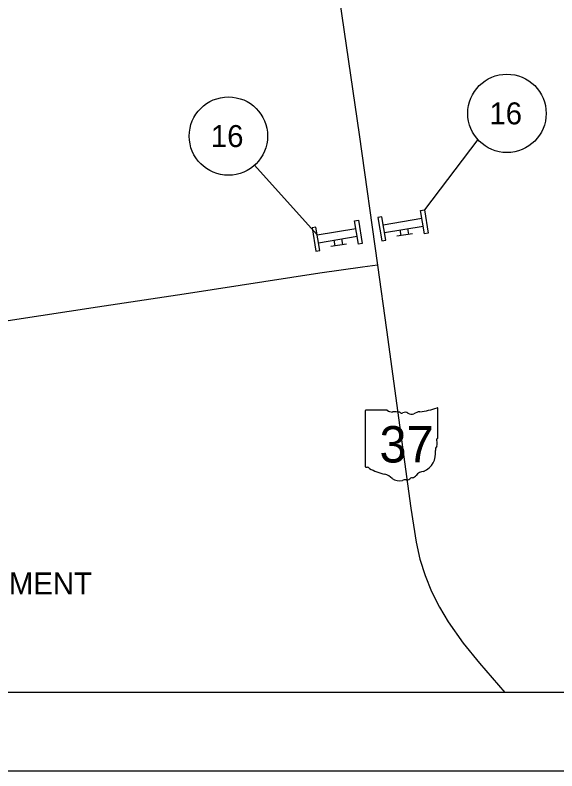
# Model space of a CAD drawing. Extents: x 0 to 860, y 0 to 513.
# Drawn here: x 543.6 to 612.7, y 0 to 96.5 of the extents above; entities that cross this region are included whole.
import ezdxf

# ---------------------------------------------------------------- set-up
doc = ezdxf.new("R2010")
doc.units = 0
for name, color, linetype in [('GM_X_State_Route', 7, 'Continuous'), ('GM_X_State_Shield', 7, 'Continuous'), ('MT_P_Cells', 7, 'Continuous'), ('MT_P_Text', 7, 'Continuous'), ('SH_Border', 7, 'Continuous'), ('SH_Cut_Line', 7, 'Continuous'), ('SH_Text', 7, 'Continuous')]:
    doc.layers.add(name, color=color, linetype=linetype)

msp = doc.modelspace()

# ---------------------------------------------------------------- linework, layer by layer
at = {"layer": 'GM_X_State_Route'}
for p, q in [((602.614, 80.579), (595.8, 71.598)), ((574.144, 77.301), (582.122, 68.405))]:
    msp.add_line(p, q, dxfattribs=at)
msp.add_lwpolyline([(562.698, 192.909), (570.661, 166.428), (575.44, 147.058), (579.85, 129.649), (582.628, 114.786), (585.257, 96.374), (587.475, 81.221), (589.804, 64.545), (590.968, 56.308), (594.05, 33.537), (594.743, 29.195), (595.231, 27.041), (595.885, 24.93), (596.718, 22.881), (597.709, 20.902), (598.844, 19.007), (600.762, 16.311), (602.842, 13.754), (606.072, 10)], dxfattribs=at)
for centre in [(606.332, 83.923), (570.805, 81.023)]:
    msp.add_circle(centre, 5, dxfattribs=at)
at = {"layer": 'GM_X_State_Shield'}
for p, q in [((588.246, 45.911), (588.246, 38.866)), ((591.055, 46.032), (588.337, 46.032)), ((597.527, 42.521), (597.527, 46.206)), ((597.526, 42.522), (597.527, 42.521))]:
    msp.add_line(p, q, dxfattribs=at)
for centre, radius, start, end in [((594.221, 55.635), 9.842, 275.84447, 288.90645), ((597.424, 46.222), 0.103, 351.86209, 97.738), ((588.352, 45.926), 0.108, 98.1301, 188.1301), ((591.703, 46.849), 1.043, 231.61951, 271.11188), ((592.048, 42.077), 3.744, 80.48669, 94.98827), ((592.898, 45.962), 0.301, 219.79206, 297.10237), ((593.34, 45.148), 0.626, 54.46668, 119.14113), ((594.147, 46.265), 0.753, 233.85621, 294.82819), ((595.476, 43.88), 1.98, 97.34618, 120.76885), ((597.417, 42.507), 0.111, 289.60381, 7.73413), ((597.503, 42.251), 0.16, 107.94398, 210.33697), ((596.486, 41.785), 0.96, 340.03296, 23.64957), ((594.772, 40.51), 2.462, 292.30889, 8.98584), ((597.897, 40.979), 0.698, 136.8065, 186.92959), ((588.353, 38.851), 0.108, 171.95839, 258.30661), ((588.37, 39.572), 0.828, 267.33899, 280.60386), ((588.539, 38.46), 0.298, 29.74838, 93.27175), ((592.308, 44.789), 7.108, 240.41292, 257.1985), ((590.189, 35.702), 2.224, 47.18416, 75.83597), ((594.102, 38.184), 0.795, 282.87319, 323.27711), ((595.81, 36.889), 1.348, 94.40312, 142.57675), ((592.594, 38.425), 1.411, 230.70037, 286.29184), ((593.409, 35.989), 1.16, 85.69512, 111.20995), ((593.512, 37.897), 0.752, 268.77702, 315.54927), ((594.192, 37.215), 0.212, 65.75173, 132.64842)]:
    msp.add_arc(centre, radius, start, end, dxfattribs=at)
at = {"layer": 'MT_P_Cells'}
for p, q in [((590.536, 69.715), (595.47, 70.53)), ((590.699, 68.728), (595.633, 69.543)), ((593.085, 69.629), (593.085, 69.629)), ((582.122, 68.405), (587.056, 69.22)), ((594.275, 68.558), (592.302, 68.233)), ((592.673, 69.054), (592.795, 68.314)), ((593.659, 69.217), (593.782, 68.477)), ((582.285, 67.418), (587.218, 68.233)), ((584.259, 67.744), (584.381, 67.004)), ((584.67, 68.319), (584.67, 68.319)), ((585.245, 67.907), (585.367, 67.167)), ((585.861, 67.249), (583.888, 66.923))]:
    msp.add_line(p, q, dxfattribs=at)
for points in [[(595.8, 71.598), (596.289, 68.638), (595.796, 68.556), (595.307, 71.516)], [(589.88, 70.62), (590.369, 67.66), (590.862, 67.741), (590.373, 70.701)], [(587.386, 70.288), (587.875, 67.328), (587.381, 67.247), (586.893, 70.206)], [(581.466, 69.31), (581.955, 66.35), (582.448, 66.432), (581.959, 69.392)]]:
    msp.add_lwpolyline(points, close=True, dxfattribs=at)
at = {"layer": 'MT_P_Text'}
msp.add_lwpolyline([(589.804, 64.545), (587.891, 64.276), (582.477, 63.515), (565.181, 60.849), (554.129, 59.174), (535.454, 56.346), (520.841, 54.13), (508.954, 52.273), (498.14, 50.632), (484.078, 48.515), (472.182, 46.722), (456.987, 44.416), (438.659, 41.636), (430.006, 40.339), (421.349, 39.075), (413.788, 37.881), (408.51, 37.039), (379.628, 190.643)], dxfattribs=at)
at = {"layer": 'SH_Border'}
for points in [[(30, 430), (670, 430), (670, 10), (30, 10)], [(335, 430), (640, 430), (640, 10), (335, 10)]]:
    msp.add_lwpolyline(points, close=True, dxfattribs=at)
at = {"layer": 'SH_Cut_Line'}
msp.add_lwpolyline([(0, 0), (680, 0), (680, 440), (0, 440)], close=True, dxfattribs=at)

# ---------------------------------------------------------------- texts
at = {"layer": 'GM_X_State_Route'}
for p in [(604.09, 82.523), (568.564, 79.623)]:
    msp.add_text('16', height=2.8, dxfattribs=at).set_placement(p)
at = {"layer": 'GM_X_State_Shield'}
msp.add_text('37', height=4.6406, dxfattribs=at).set_placement((590.075, 39.363))
at = {"layer": 'SH_Text'}
msp.add_text('DESIGNATED LOCAL DETOUR DETAIL ENLARGEMENT', height=2.8, dxfattribs=at).set_placement((455.21, 22.521))

doc.saveas('drawing.dxf')
